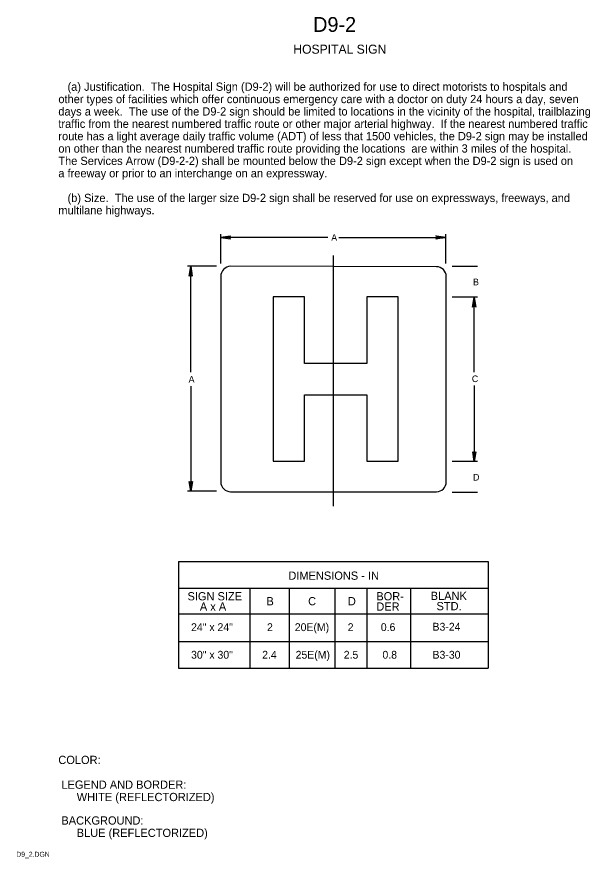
# Model space of a CAD drawing. Extents: x 0.013 to 0.187, y 0.004 to 0.259.
import ezdxf

# ---------------------------------------------------------------- set-up
doc = ezdxf.new("R2010")
doc.units = 0
for name, color, linetype in [('1', 7, 'Continuous'), ('2', 7, 'Continuous'), ('3', 7, 'Continuous')]:
    doc.layers.add(name, color=color, linetype=linetype)

# ---------------------------------------------------------------- blocks, each defined once
blk = doc.blocks.new('RARROW')
at = {"layer": '3'}
for p, q in [((-2.156, 0.28500000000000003), (-2.2665, 0.384625)), ((-2.2665, 0.384625), (0, 0)), ((0, 0), (-2.2665, -0.379125)), ((-2.156, 0.28500000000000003), (-2.075625, 0.12075)), ((0, 0), (-2.156, 0.28500000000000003)), ((-2.14975, -0.2705), (0, 0)), ((-2.075625, 0.12075), (0, 0)), ((0, 0), (-2.074, -0.108)), ((-2.2665, -0.379125), (-2.14975, -0.2705)), ((-2.074, -0.108), (-2.14975, -0.2705))]:
    blk.add_line(p, q, dxfattribs=at)

msp = doc.modelspace()

# ---------------------------------------------------------------- linework, layer by layer
at = {"layer": '2'}
for p, q in [((0.0745, 0.184375), (0.0745, 0.19325)), ((0.107, 0.19225), (0.0745, 0.19225)), ((0.11025, 0.19225), (0.14275000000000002, 0.19225)), ((0.14275000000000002, 0.184375), (0.14275000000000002, 0.19325)), ((0.07325, 0.1835), (0.064375, 0.1835)), ((0.065375, 0.151375), (0.065375, 0.1835)), ((0.144625, 0.1835), (0.152375, 0.1835)), ((0.144625, 0.17425000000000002), (0.152375, 0.17425000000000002)), ((0.151375, 0.17025), (0.151375, 0.17425000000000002)), ((0.151375, 0.151375), (0.151375, 0.17425000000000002)), ((0.065375, 0.147125), (0.065375, 0.11525)), ((0.151375, 0.147375), (0.151375, 0.124375)), ((0.151375, 0.128375), (0.151375, 0.124375)), ((0.144625, 0.124375), (0.152375, 0.124375)), ((0.07325, 0.11525), (0.064375, 0.11525)), ((0.144625, 0.115), (0.152375, 0.115))]:
    msp.add_line(p, q, dxfattribs=at)
at = {"layer": '3'}
for p, q in [((0.108625, 0.18675), (0.108625, 0.11075)), ((0.139875, 0.183375), (0.0775, 0.1835)), ((0.0775, 0.1835), (0.0775, 0.1835)), ((0.0745, 0.180375), (0.0745, 0.11812500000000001)), ((0.142875, 0.11812500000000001), (0.142875, 0.180375)), ((0.099875, 0.17425000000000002), (0.090375, 0.17425000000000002)), ((0.090375, 0.17425000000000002), (0.090375, 0.124375)), ((0.099875, 0.17425000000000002), (0.090375, 0.17425000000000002)), ((0.090375, 0.17425000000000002), (0.090375, 0.124375)), ((0.099875, 0.154), (0.099875, 0.17425000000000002)), ((0.099875, 0.154), (0.099875, 0.17425000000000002)), ((0.12825, 0.17425000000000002), (0.11875000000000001, 0.17425000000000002)), ((0.11875000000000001, 0.17425000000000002), (0.11875000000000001, 0.154)), ((0.12825, 0.17425000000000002), (0.11875000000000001, 0.17425000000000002)), ((0.11875000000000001, 0.17425000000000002), (0.11875000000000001, 0.154)), ((0.12825, 0.124375), (0.12825, 0.17425000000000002)), ((0.12825, 0.124375), (0.12825, 0.17425000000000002)), ((0.11875000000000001, 0.154), (0.099875, 0.154)), ((0.11875000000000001, 0.154), (0.099875, 0.154)), ((0.108625, 0.14925), (0.108625, 0.14925)), ((0.099875, 0.124375), (0.099875, 0.1445)), ((0.099875, 0.1445), (0.11875000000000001, 0.1445)), ((0.099875, 0.124375), (0.099875, 0.1445)), ((0.099875, 0.1445), (0.11875000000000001, 0.1445)), ((0.11875000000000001, 0.1445), (0.11875000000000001, 0.124375)), ((0.11875000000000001, 0.1445), (0.11875000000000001, 0.124375)), ((0.090375, 0.124375), (0.099875, 0.124375)), ((0.090375, 0.124375), (0.099875, 0.124375)), ((0.11875000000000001, 0.124375), (0.12825, 0.124375)), ((0.11875000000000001, 0.124375), (0.12825, 0.124375)), ((0.0775, 0.115125), (0.139875, 0.115125)), ((0.06170858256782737, 0.09391265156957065), (0.15554141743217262, 0.09391265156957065)), ((0.06170858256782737, 0.09391265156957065), (0.06170858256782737, 0.06153765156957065)), ((0.15554141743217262, 0.09391265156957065), (0.15554141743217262, 0.06153765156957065)), ((0.15554141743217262, 0.08578765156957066), (0.061629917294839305, 0.08578765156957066)), ((0.08332934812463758, 0.08575521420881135), (0.08332934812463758, 0.061537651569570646)), ((0.09526833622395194, 0.08575521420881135), (0.09526833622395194, 0.06153765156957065)), ((0.10906410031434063, 0.08575521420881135), (0.10906410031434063, 0.06153765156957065)), ((0.11878651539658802, 0.08577818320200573), (0.11878651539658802, 0.06153765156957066)), ((0.13202559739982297, 0.08575521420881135), (0.13202559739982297, 0.06153765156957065)), ((0.061677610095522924, 0.07803765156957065), (0.15554141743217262, 0.07803765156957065)), ((0.06172914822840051, 0.06966265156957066), (0.15554141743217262, 0.06966265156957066)), ((0.0616560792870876, 0.06153765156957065), (0.15554141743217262, 0.06153765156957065))]:
    msp.add_line(p, q, dxfattribs=at)
for centre, radius, start, end in [((0.07756962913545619, 0.18043065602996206), 0.003070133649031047, 91.29955277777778, 181.0387277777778), ((0.13987500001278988, 0.18037500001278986), 0.002999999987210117, 0, 90), ((0.07749999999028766, 0.11812499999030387), 0.0029999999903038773, 180, 270), ((0.1398749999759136, 0.11812500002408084), 0.0030000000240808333, 270, 0)]:
    msp.add_arc(centre, radius, start, end, dxfattribs=at)

# ---------------------------------------------------------------- block references
at = {"layer": '2', "xscale": 0.0013236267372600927, "yscale": 0.001309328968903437}
for p, rotation in [((0.0745, 0.19225), 180), ((0.065375, 0.1835), 90), ((0.151375, 0.174125), 90), ((0.151375, 0.174125), 90), ((0.151375, 0.12425), -90), ((0.151375, 0.12425), -90), ((0.065375, 0.11525), -90)]:
    msp.add_blockref('RARROW', p, dxfattribs=dict(at, rotation=rotation))
msp.add_blockref('RARROW', (0.14275000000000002, 0.19225), dxfattribs=at)

# ---------------------------------------------------------------- texts
at = {"layer": '1'}
for s, height, p in [('D9-2', 0.0045000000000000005, (0.10250000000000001, 0.254625)), ('HOSPITAL SIGN', 0.00275025, (0.0965, 0.248)), ('COLOR:', 0.0024997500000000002, (0.02525, 0.0325)), (' LEGEND AND BORDER:', 0.0024997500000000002, (0.02525, 0.025)), ('      WHITE (REFLECTORIZED)', 0.0024997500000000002, (0.02525, 0.02125)), (' BACKGROUND:', 0.0024997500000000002, (0.02525, 0.014125)), ('      BLUE (REFLECTORIZED)', 0.0024997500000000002, (0.02525, 0.010375)), ('D9_2.DGN', 0.0015, (0.0125, 0.004375))]:
    msp.add_text(s, height=height, dxfattribs=at).set_placement(p)
at = {"layer": '2'}
for s, height, p in [('   (a) Justification.  The Hospital Sign (D9-2) will be authorized for use to direct motorists to hospitals and', 0.0024997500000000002, (0.02525, 0.236748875)), ('other types of facilities which offer continuous emergency care with a doctor on duty 24 hours a day, seven', 0.0024997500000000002, (0.02525, 0.232999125)), ('days a week.  The use of the D9-2 sign should be limited to locations in the vicinity of the hospital, trailblazing', 0.0024997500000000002, (0.02525, 0.22924937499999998)), ('traffic from the nearest numbered traffic route or other major arterial highway.  If the nearest numbered traffic', 0.0024997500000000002, (0.02525, 0.225499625)), ('route has a light average daily traffic volume (ADT) of less that 1500 vehicles, the D9-2 sign may be installed', 0.0024997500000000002, (0.02525, 0.221749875)), ('on other than the nearest numbered traffic route providing the locations  are within 3 miles of the hospital.  ', 0.0024997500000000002, (0.02525, 0.218000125)), ('The Services Arrow (D9-2-2) shall be mounted below the D9-2 sign except when the D9-2 sign is used on ', 0.0024997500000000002, (0.02525, 0.214250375)), ('a freeway or prior to an interchange on an expressway.', 0.0024997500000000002, (0.02525, 0.21050062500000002)), ('   (b) Size.  The use of the larger size D9-2 sign shall be reserved for use on expressways, freeways, and', 0.0024997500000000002, (0.02525, 0.203001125)), ('multilane highways.', 0.0024997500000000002, (0.02525, 0.199251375)), ('A', 0.00200025, (0.108, 0.19125))]:
    msp.add_text(s, height=height, dxfattribs=at).set_placement(p)
at = {"layer": '3'}
for s, height, p in [('B', 0.00200025, (0.151, 0.17775)), ('A', 0.00200025, (0.06475, 0.14825)), ('C', 0.00200025, (0.150625, 0.148375)), ('D', 0.00200025, (0.151, 0.11850000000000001)), ('DIMENSIONS - IN', 0.0024997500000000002, (0.09498810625, 0.08840318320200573)), ('SIGN SIZE', 0.0024997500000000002, (0.06441151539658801, 0.08215318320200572)), ('BOR-', 0.0024997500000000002, (0.12166151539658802, 0.08215318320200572)), ('BLANK', 0.0024997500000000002, (0.13816151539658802, 0.08227818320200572)), ('B', 0.0024997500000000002, (0.08835065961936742, 0.08065318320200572)), ('C', 0.0024997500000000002, (0.10098819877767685, 0.08065318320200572)), ('D', 0.0024997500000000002, (0.11303651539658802, 0.08065318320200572)), ('STD.', 0.0024997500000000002, (0.13991151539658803, 0.07915318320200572)), ('A x A', 0.0024997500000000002, (0.06816151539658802, 0.07902818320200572)), ('DER', 0.0024997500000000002, (0.12166151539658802, 0.07902818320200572)), ('24" x 24"', 0.0023752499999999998, (0.06549552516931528, 0.07284055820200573)), ('2', 0.0023752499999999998, (0.08852030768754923, 0.07284055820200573)), ('20E(M)', 0.0023752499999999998, (0.09694848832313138, 0.07284055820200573)), ('2', 0.0023752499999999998, (0.11298504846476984, 0.07284055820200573)), ('0.6', 0.0023752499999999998, (0.12303002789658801, 0.07284055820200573)), ('B3-24', 0.0023752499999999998, (0.1387001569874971, 0.07296555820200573)), ('30" x 30"', 0.0023752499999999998, (0.06549552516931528, 0.06446555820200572)), ('2.4', 0.0023752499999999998, (0.08705377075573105, 0.06446555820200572)), ('25E(M)', 0.0023752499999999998, (0.09719848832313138, 0.06446555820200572)), ('2.5', 0.0023752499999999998, (0.11178290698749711, 0.06446555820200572)), ('0.8', 0.0023752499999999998, (0.1235170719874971, 0.06446555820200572)), ('B3-30', 0.0023752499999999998, (0.13870663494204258, 0.06446555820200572))]:
    msp.add_text(s, height=height, dxfattribs=at).set_placement(p)

doc.saveas('drawing.dxf')
